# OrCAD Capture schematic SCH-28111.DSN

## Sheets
1 ARDUINO_HEADERS: size C; title: TWR-SHIELD; rev: B; company: Freescale Semiconductor; note: SCH-28111 PDF: SPF-28111; note: 6501 William Cannon Drive West; note: Austin, TX 78735-8598
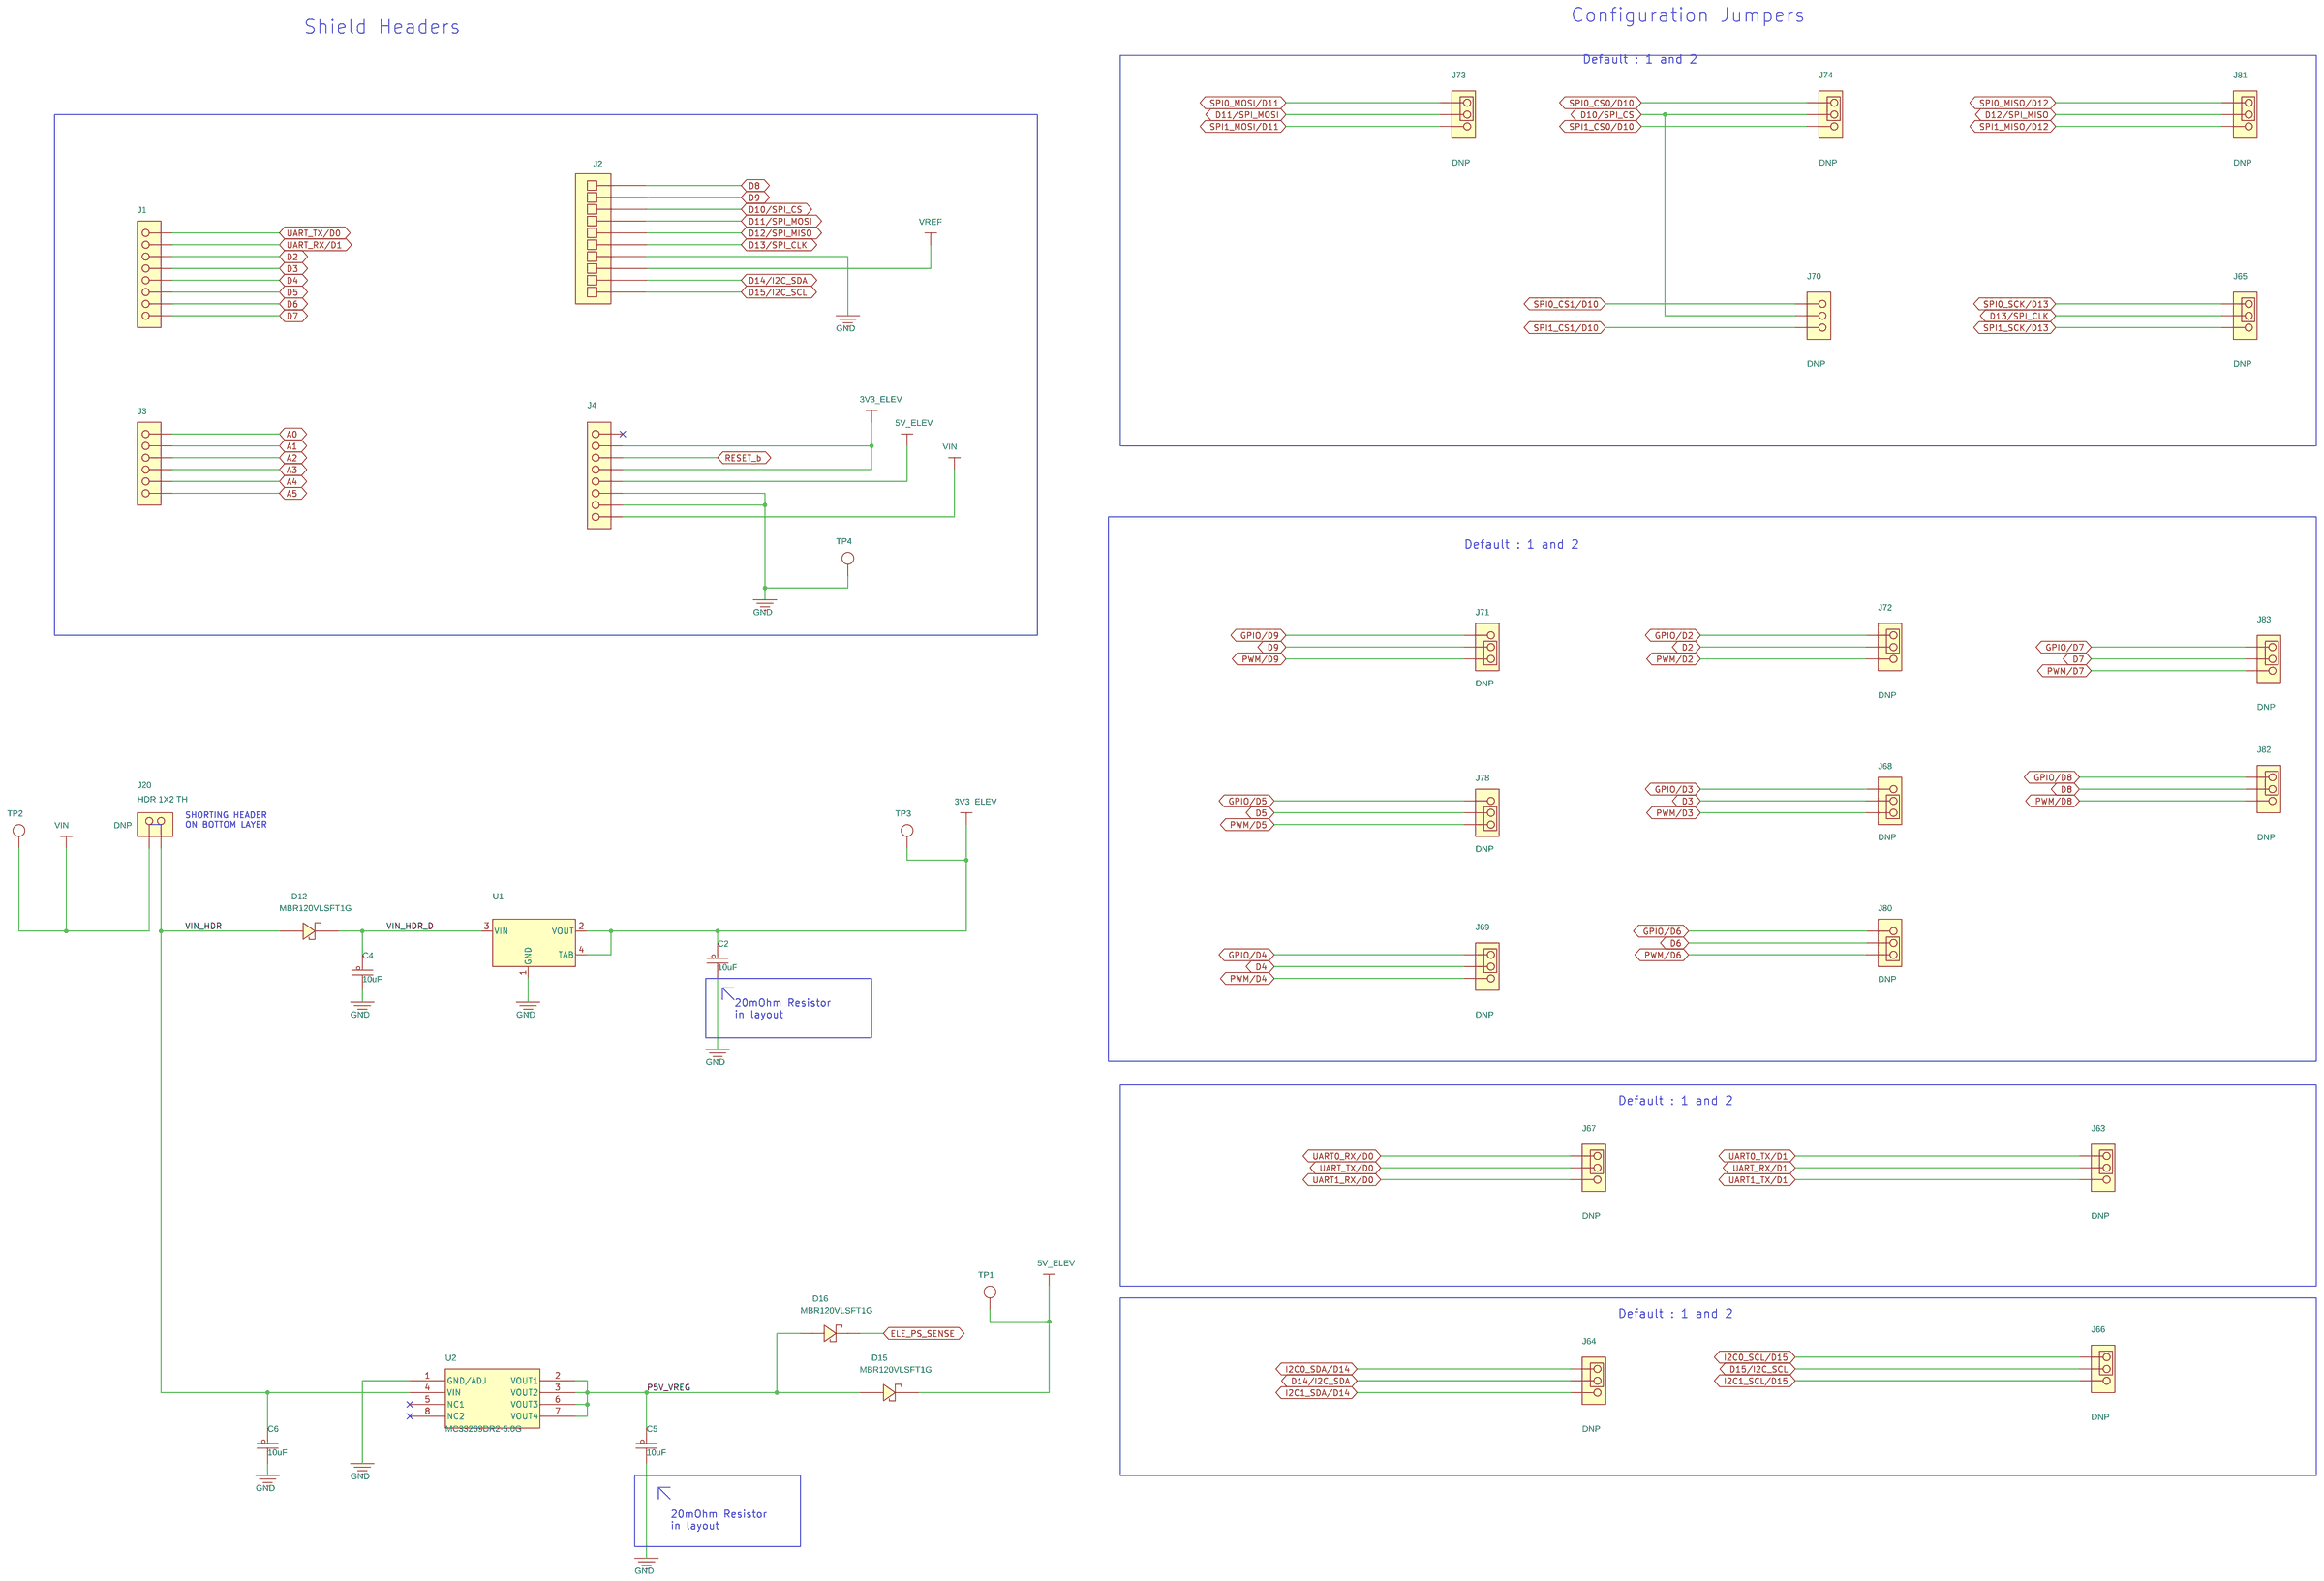
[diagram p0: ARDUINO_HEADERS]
2 ELEVATOR_CONNECTORS: size C
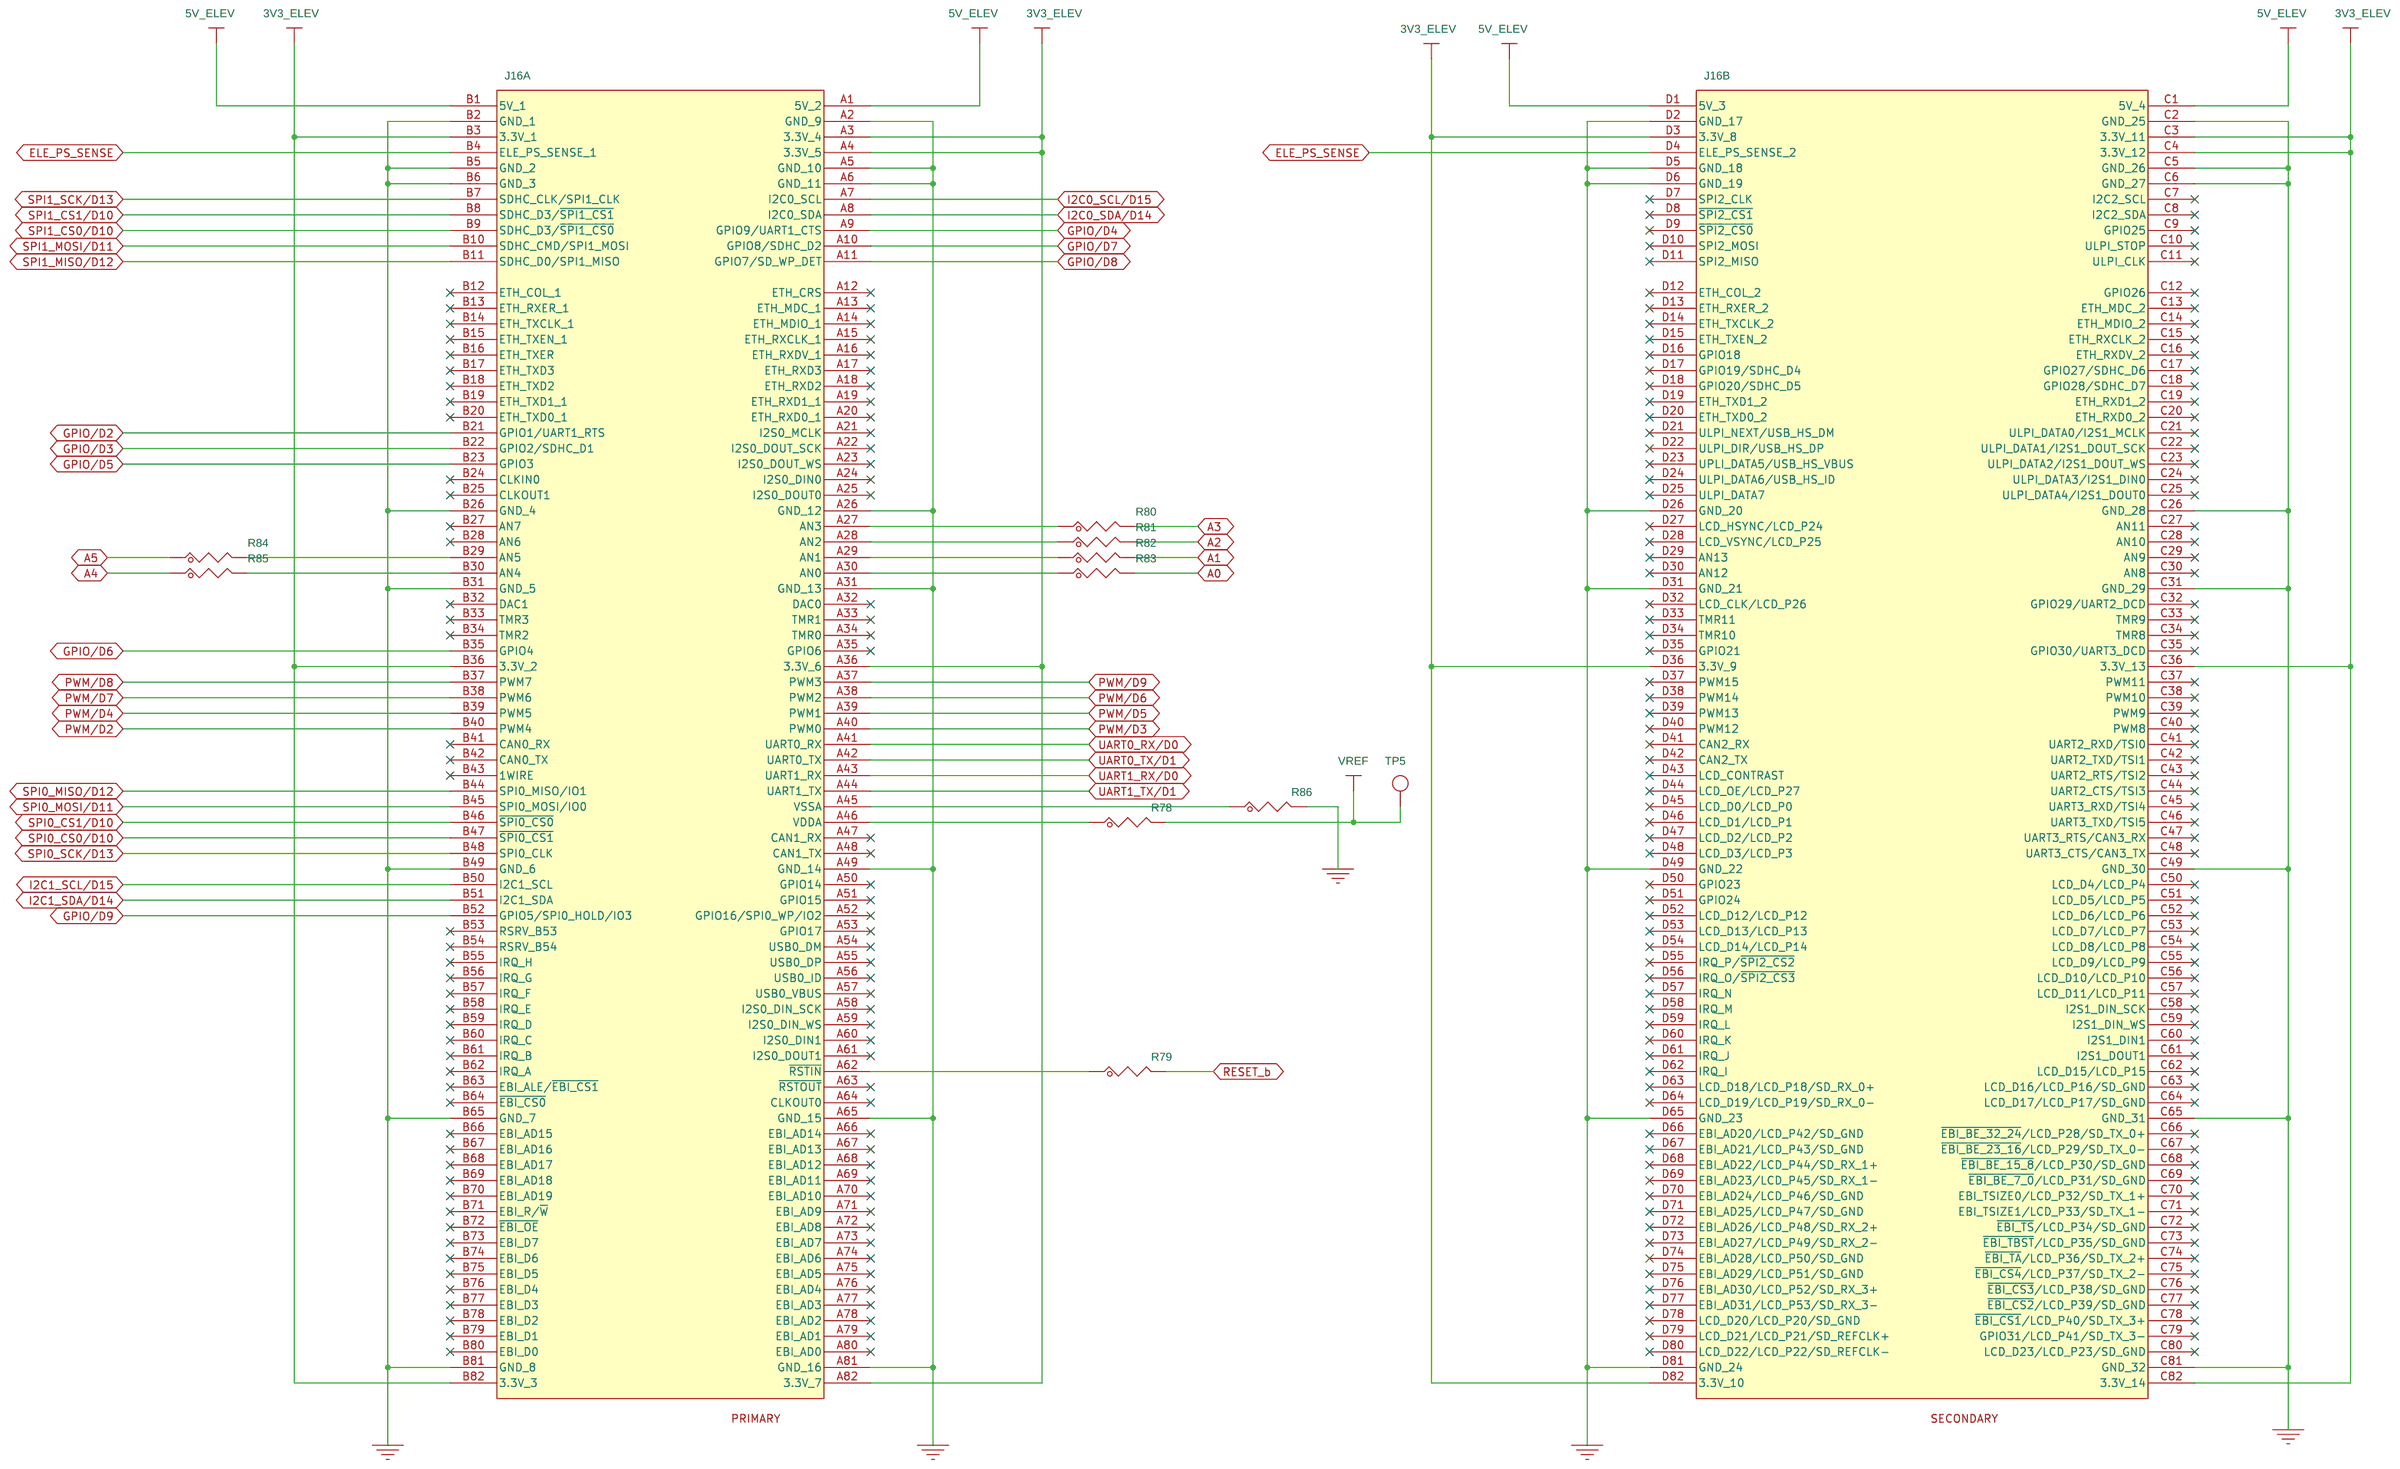
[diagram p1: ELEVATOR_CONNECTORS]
3 01_TABLE_OF_CONTENTS/ REVISION
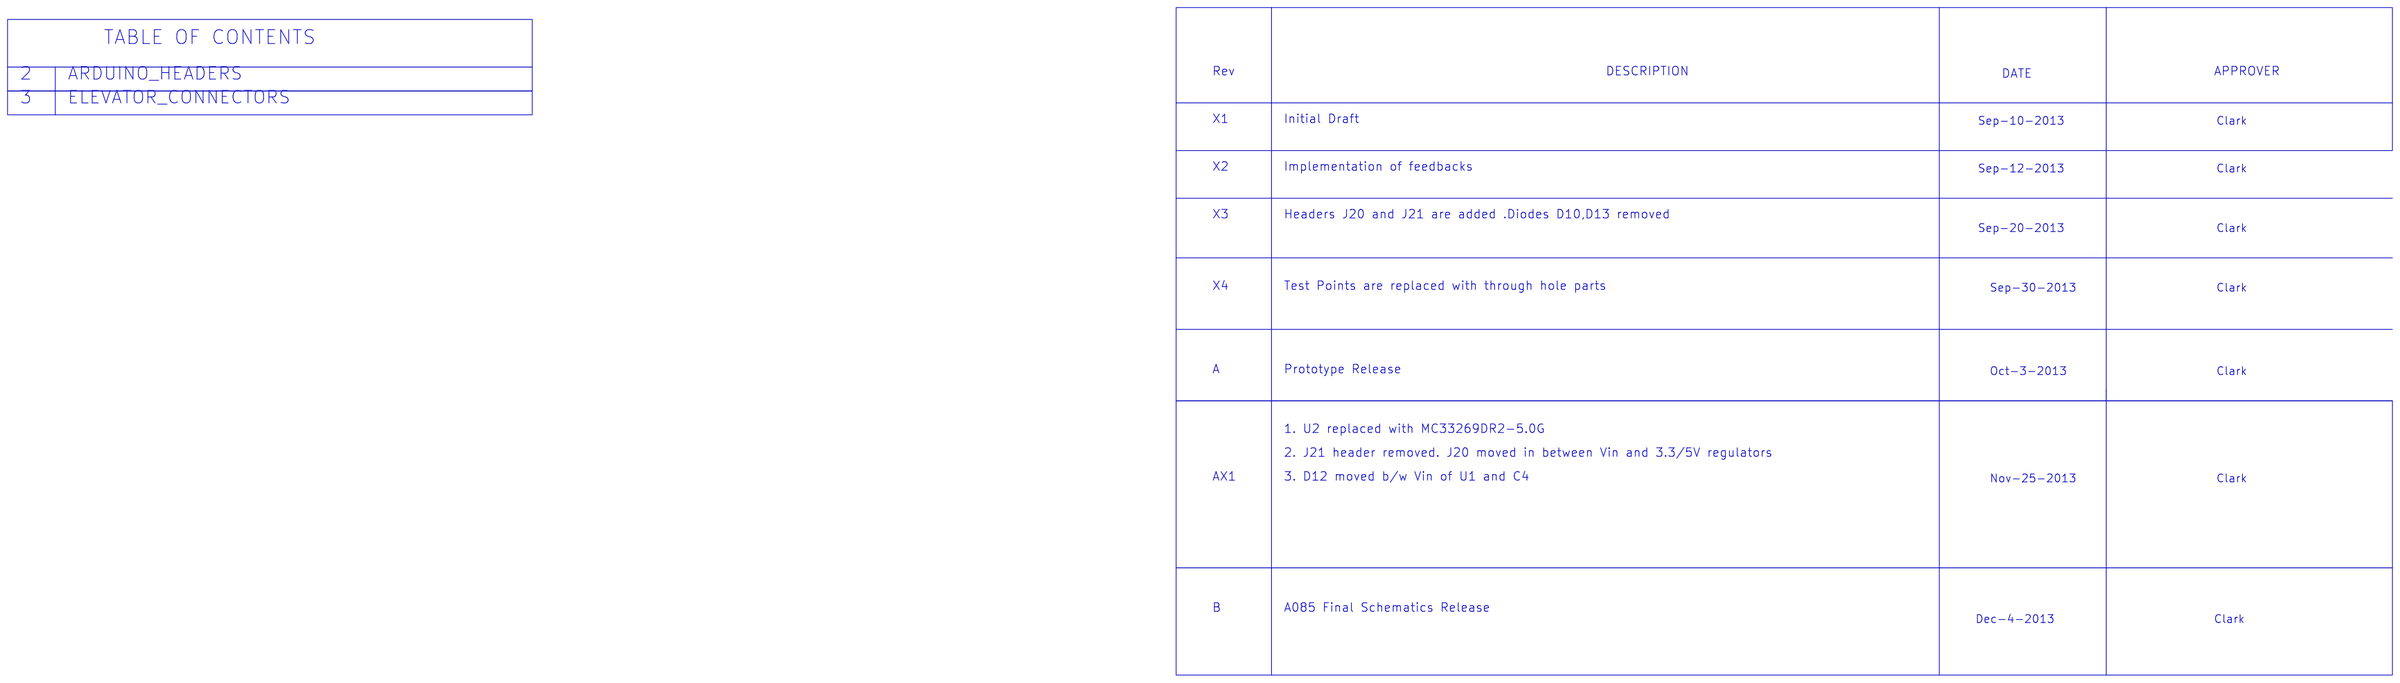
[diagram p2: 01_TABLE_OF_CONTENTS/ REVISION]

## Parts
sheet ARDUINO_HEADERS
C2  10uF  [CC0603_OV]
C4  10uF  [CC0603_OV]
C5  10uF  [CC0603_OV]
C6  10uF  [CC0603_OV]
D12  MBR120VLSFT1G  [SOD-123]
D15  MBR120VLSFT1G  [SOD-123]
D16  MBR120VLSFT1G  [SOD-123]
J1  CON_1X8  [con_1x8_skt_2p54_th]
J2  CON_1X10  [HDR110]
J3  CON_1X6  [con_skt1x6_th]
J4  CON_1X8  [con_1x8_skt_2p54_th]
J20  HDR 1X2 TH  [SH_HDR102_BOTTOM]
J63  HDR 1x3 TH  [hdr103_short1_2]
J64  HDR 1x3 TH  [hdr103_short1_2]
J65  HDR 1x3 TH  [hdr103_short1_2]
J66  HDR 1x3 TH  [hdr103_short1_2]
J67  HDR 1x3 TH  [hdr103_short1_2]
J68  HDR 1x3 TH  [hdr103_short1_2]
J69  HDR 1x3 TH  [hdr103_short1_2]
J70  HDR_1X3  [HDR103]
J71  HDR 1x3 TH  [hdr103_short1_2]
J72  HDR 1x3 TH  [hdr103_short1_2]
J73  HDR 1x3 TH  [hdr103_short1_2]
J74  HDR 1x3 TH  [hdr103_short1_2]
J78  HDR 1x3 TH  [hdr103_short1_2]
J80  HDR 1x3 TH  [hdr103_short1_2]
J81  HDR 1x3 TH  [hdr103_short1_2]
J82  HDR 1x3 TH  [hdr103_short1_2]
J83  HDR 1x3 TH  [hdr103_short1_2]
TP1  TEST POINT WHITE  [TEST_LOOP]
TP2  TEST POINT WHITE  [TEST_LOOP]
TP3  TEST POINT WHITE  [TEST_LOOP]
TP4  TEST POINT WHITE  [TEST_LOOP]
U1  NCP1117ST33T3G  [sot223]
U2  MC33269DR2-5.0G  [so8_1p27_4x5]
sheet ELEVATOR_CONNECTORS
J16  PCI EXPRESS TOWER SYSTEM  [cn2x82_finger_ass]  (sections A,B)
R78  0  [RC0402_25]
R79  0  [RC0402_25]
R80  0  [RC0402_25]
R81  0  [RC0402_25]
R82  0  [RC0402_25]
R83  0  [RC0402_25]
R84  0  [RC0402_25]
R85  0  [RC0402_25]
R86  0  [RC0402_25]
TP5  TEST POINT WHITE  [TEST_LOOP]

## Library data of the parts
C2 C4-C6 = CAP_NP: CAP CER 10UF 10V 20% X5R 0603; AGILE_PN: 150-78609; CAD_APPROVED: Yes; FPLIST: CC0603_OV,CC0603,0603_CC; HEIGHT: 1.016MM; MFG_NAME01: TAIYO YUDEN; MFG_PN01: LMK107BJ106MALTD; ROHS: Yes; VOLTAGE: 10V
D12 D15 D16 = DIODE_SCHTKY: DIODE SCH RECT 1A 20V SMT; AGILE_PN: 480-75997; CAD_APPROVED: Yes; HEIGHT: 1MM; MFG_NAME01: ON SEMICONDUCTOR; ROHS: Yes
J1 J4 = CONN_HDR_8X1: CON 1X8 SKT TH 100MIL SP 335H AU 104L; AGILE_PN: 210-79539; CAD_APPROVED: Yes; HEIGHT: 8.51MM; MFG_NAME01: SAMTEC; MFG_PN01: SSW-108-01-G-S; ROHS: Yes
J2 = RCPT_1X10: CON 1X10 SKT TH 100MIL SP 335H AU; AGILE_PN: 210-75438; CAD_APPROVED: Yes; HEIGHT: 8.51 MM; MFG_NAME01: SAMTEC; MFG_PN01: SSW-110-01-G-S; ROHS: Yes
J3 = CONN_HDR_6X1: CON 1X6 SKT TH 100MIL SP 335H AU 104L; AGILE_PN: 210-79530; CAD_APPROVED: Yes; HEIGHT: 8.76MM; MFG_NAME01: SAMTEC; MFG_PN01: SSW-106-01-G-S; ROHS: Yes
J20 = CONN_HDR_2X1: HDR 1X2 TH 100MIL SP 339H AU 98L; AGILE_PN: 210-75439; ASSY_OPT: DNP; CAD_APPROVED: YES; FPLIST: HDR102,SH_HDR102_BOTTOM; HEIGHT: 8.71 MM; MFG_NAME01: SAMTEC; MFG_PN01: TSW-102-07-G-S; ROHS: Yes
J63-J69 J71-J74 J78 J80-J83 = CONN_HDR_3X1_SHORT: HDR 1X3 TH 100MIL -- NO PART TO ORDER; AGILE_PN: 210-80431; ASSY_OPT: DNP; CAD_APPROVED: Yes; HEIGHT: 8.51 MM; MFG_NAME01: NA; MFG_PN01: NA; ROHS: Yes
J70 = CONN_HDR_3X1: HDR 1X3 TH 100MIL SP 330H AU 98L; AGILE_PN: 210-75442; ASSY_OPT: DNP; CAD_APPROVED: Yes; HEIGHT: 8.38 MM; MFG_NAME01: SAMTEC; MFG_PN01: HTSW-103-07-S-S; ROHS: Yes
TP1-TP5 = TestLoop: TEST POINT WHITE 40 MIL DRILL 180 MIL TH 109L; AGILE_PN: 210-75685; CAD_APPROVED: Yes; HEIGHT: 4.8 MM; MFG_NAME01: COMPONENTS CORPORATION; MFG_PN01: TP-105-01-09; ROHS: Yes
U1 = LD1117AS18: IC VREG LDO 1A 3.3V SOT223; AGILE_PN: 312-80039; CAD_APPROVED: Yes; HEIGHT: 1.8MM; MFG_NAME01: ON Semiconductor; ROHS: Yes
U2 = MC33269D: IC VREG LDO 5V 0.8A 0-20V SO8; AGILE_PN: 315-80046; CAD_APPROVED: Yes; HEIGHT: 1.75MM; MFG_NAME01: ON Semiconductor; ROHS: Yes
J16 = CONN_PCI_XPRESS_X16_328P: CON DUAL 2X82 Edge PCI Express SMT 1MM SP 591H FOR TOWER SYSTEM NOT A PART TO ORDER; AGILE_PN: 211-78844; CAD_APPROVED: Yes; Group: a; HEIGHT: 15.01MM; MFG_NAME01: NA; MFG_PN01: EDGE PCI EXPRESS 164; ROHS: Yes
R78-R86 = RES: RES MF ZERO OHM 1/16W 5% 0402; AGILE_PN: 470-75394; CAD_APPROVED: Yes; FPLIST: RC0402_25,RC0402_HD,RC0402_X2,0402_CC; MFG_NAME01: ROHM; MFG_PN01: MCR01MZPJ000; ROHS: Yes; Tolerance: 5%

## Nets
3V3_ELEV: C2.1 J4.2 J4.4 J16.A3(3.3V_4) J16.A4(3.3V_5) J16.A36(3.3V_6) J16.A82(3.3V_7) J16.B3(3.3V_1) J16.B36(3.3V_2) J16.B82(3.3V_3) J16.C3(3.3V_11) J16.C4(3.3V_12) J16.C36(3.3V_13) J16.C82(3.3V_14) J16.D3(3.3V_8) J16.D36(3.3V_9) J16.D82(3.3V_10) TP3.1(Pin1) U1.2(VOUT) U1.4(TAB)
5V_ELEV: D15.C J4.5 J16.A1(5V_2) J16.B1(5V_1) J16.C1(5V_4) J16.D1(5V_3) TP1.1(Pin1)
GND: C2.2 C4.2 C5.2 C6.2 J2.7 J4.6 J4.7 J16.A2(GND_9) J16.A5(GND_10) J16.A6(GND_11) J16.A26(GND_12) J16.A31(GND_13) J16.A49(GND_14) J16.A65(GND_15) J16.A81(GND_16) J16.B2(GND_1) J16.B5(GND_2) J16.B6(GND_3) J16.B26(GND_4) J16.B31(GND_5) J16.B49(GND_6) J16.B65(GND_7) J16.B81(GND_8) J16.C2(GND_25) J16.C5(GND_26) J16.C6(GND_27) J16.C26(GND_28) J16.C31(GND_29) J16.C49(GND_30) J16.C65(GND_31) J16.C81(GND_32) J16.D2(GND_17) J16.D5(GND_18) J16.D6(GND_19) J16.D26(GND_20) J16.D31(GND_21) J16.D49(GND_22) J16.D65(GND_23) J16.D81(GND_24) R86.2 TP4.1(Pin1) U1.1(GND) U2.1(GND/ADJ)
P5V_VREG: C5.1 D15.A D16.A U2.2(VOUT1) U2.3(VOUT2) U2.6(VOUT3) U2.7(VOUT4)
VIN: J4.8 J20.1 TP2.1(Pin1)
VIN_HDR: C6.1 D12.A J20.2 U2.4(VIN)
VIN_HDR_D: C4.1 D12.C U1.3(VIN)
A0: J3.1 R83.2
A1: J3.2 R82.2
A2: J3.3 R81.2
A3: J3.4 R80.2
A4: J3.5 R85.1
A5: J3.6 R84.1
D2: J1.3 J72.2
D3: J1.4 J68.2
D4: J1.5 J69.2
D5: J1.6 J78.2
D6: J1.7 J80.2
D7: J1.8 J83.2
D8: J2.1 J82.2
D9: J2.2 J71.2
D10/SPI_CS: J2.3 J70.2 J74.2
D11/SPI_MOSI: J2.4 J73.2
D12/SPI_MISO: J2.5 J81.2
D13/SPI_CLK: J2.6 J65.2
D14/I2C_SDA: J2.9 J64.2
D15/I2C_SCL: J2.10 J66.2
ELE_PS_SENSE: D16.C J16.B4(ELE_PS_SENSE_1) J16.D4(ELE_PS_SENSE_2)
GPIO/D2: J16.B21(GPIO1/UART1_RTS) J72.1
GPIO/D3: J16.B22(GPIO2/SDHC_D1) J68.3
GPIO/D4: J16.A9(GPIO9/UART1_CTS) J69.1
GPIO/D5: J16.B23(GPIO3) J78.3
GPIO/D6: J16.B35(GPIO4) J80.3
GPIO/D7: J16.A10(GPIO8/SDHC_D2) J83.1
GPIO/D8: J16.A11(GPIO7/SD_WP_DET) J82.1
GPIO/D9: J16.B52(GPIO5/SPI0_HOLD/IO3) J71.3
I2C0_SCL/D15: J16.A7(I2C0_SCL) J66.1
I2C0_SDA/D14: J16.A8(I2C0_SDA) J64.1
I2C1_SCL/D15: J16.B50(I2C1_SCL) J66.3
I2C1_SDA/D14: J16.B51(I2C1_SDA) J64.3
PWM/D2: J16.B40(PWM4) J72.3
PWM/D3: J16.A40(PWM0) J68.1
PWM/D4: J16.B39(PWM5) J69.3
PWM/D5: J16.A39(PWM1) J78.1
PWM/D6: J16.A38(PWM2) J80.1
PWM/D7: J16.B38(PWM6) J83.3
PWM/D8: J16.B37(PWM7) J82.3
PWM/D9: J16.A37(PWM3) J71.1
RESET_b: J4.3 R79.2
SPI0_CS0/D10: J16.B47(~{SPI0_CS1}) J74.1
SPI0_CS1/D10: J16.B46(~{SPI0_CS0}) J70.1
SPI0_MISO/D12: J16.B44(SPI0_MISO/IO1) J81.1
SPI0_MOSI/D11: J16.B45(SPI0_MOSI/IO0) J73.1
SPI0_SCK/D13: J16.B48(SPI0_CLK) J65.1
SPI1_CS0/D10: J16.B9(SDHC_D3/~{SPI1_CS0}) J74.3
SPI1_CS1/D10: J16.B8(SDHC_D3/~{SPI1_CS1}) J70.3
SPI1_MISO/D12: J16.B11(SDHC_D0/SPI1_MISO) J81.3
SPI1_MOSI/D11: J16.B10(SDHC_CMD/SPI1_MOSI) J73.3
SPI1_SCK/D13: J16.B7(SDHC_CLK/SPI1_CLK) J65.3
UART0_RX/D0: J16.A41(UART0_RX) J67.1
UART0_TX/D1: J16.A42(UART0_TX) J63.1
UART1_RX/D0: J16.A43(UART1_RX) J67.3
UART1_TX/D1: J16.A44(UART1_TX) J63.3
UART_RX/D1: J1.2 J63.2
UART_TX/D0: J1.1 J67.2
VREF: J2.8 R78.2 TP5.1(Pin1)
N13251626: J16.B29(AN5) R84.2
N13251632: J16.B30(AN4) R85.2
N13255265: J16.A27(AN3) R80.1
N13255295: J16.A28(AN2) R81.1
N13255352: J16.A29(AN1) R82.1
N13255371: J16.A30(AN0) R83.1
N13256362: J16.A46(VDDA) R78.1
N13260720: J16.A62(~{RSTIN}) R79.1
N13275722: J16.A45(VSSA) R86.1

Not connected (* = marked no-connect by the designer): J4 1*; J16 A12(ETH_CRS)* A13(ETH_MDC_1)* A14(ETH_MDIO_1)* A15(ETH_RXCLK_1)* A16(ETH_RXDV_1)* A17(ETH_RXD3)* A18(ETH_RXD2)* A19(ETH_RXD1_1)* A20(ETH_RXD0_1)* A21(I2S0_MCLK)* A22(I2S0_DOUT_SCK)* A23(I2S0_DOUT_WS)* A24(I2S0_DIN0)* A25(I2S0_DOUT0)* A32(DAC0)* A33(TMR1)* A34(TMR0)* A35(GPIO6)* A47(CAN1_RX)* A48(CAN1_TX)* A50(GPIO14)* A51(GPIO15)* A52(GPIO16/SPI0_WP/IO2)* A53(GPIO17)* A54(USB0_DM)* A55(USB0_DP)* A56(USB0_ID)* A57(USB0_VBUS)* A58(I2S0_DIN_SCK)* A59(I2S0_DIN_WS)* A60(I2S0_DIN1)* A61(I2S0_DOUT1)* A63(~{RSTOUT})* A64(CLKOUT0)* A66(EBI_AD14)* A67(EBI_AD13)* A68(EBI_AD12)* A69(EBI_AD11)* A70(EBI_AD10)* A71(EBI_AD9)* A72(EBI_AD8)* A73(EBI_AD7)* A74(EBI_AD6)* A75(EBI_AD5)* A76(EBI_AD4)* A77(EBI_AD3)* A78(EBI_AD2)* A79(EBI_AD1)* A80(EBI_AD0)* B12(ETH_COL_1)* B13(ETH_RXER_1)* B14(ETH_TXCLK_1)* B15(ETH_TXEN_1)* B16(ETH_TXER)* B17(ETH_TXD3)* B18(ETH_TXD2)* B19(ETH_TXD1_1)* B20(ETH_TXD0_1)* B24(CLKIN0)* B25(CLKOUT1)* B27(AN7)* B28(AN6)* B32(DAC1)* B33(TMR3)* B34(TMR2)* B41(CAN0_RX)* B42(CAN0_TX)* B43(1WIRE)* B53(RSRV)* B54(RSRV)* B55(IRQ_H)* B56(IRQ_G)* B57(IRQ_F)* B58(IRQ_E)* B59(IRQ_D)* B60(IRQ_C)* B61(IRQ_B)* B62(IRQ_A)* B63(EBI_ALE/~{EBI_CS1})* B64(~{EBI_CS0})* B66(EBI_AD15)* B67(EBI_AD16)* B68(EBI_AD17)* B69(EBI_AD18)* B70(EBI_AD19)* B71(EBI_R/~{W})* B72(~{EBI_OE})* B73(EBI_D7)* B74(EBI_D6)* B75(EBI_D5)* B76(EBI_D4)* B77(EBI_D3)* B78(EBI_D2)* B79(EBI_D1)* B80(EBI_D0)* C7(I2C2_SCL)* C8(I2C2_SDA)* C9(GPIO25)* C10(ULPI_STOP)* C11(ULPI_CLK)* C12(GPIO26)* C13(ETH_MDC_2)* C14(ETH_MDIO_2)* C15(ETH_RXCLK_2)* C16(ETH_RXDV_2)* C17(GPIO27/SDHC_D6)* C18(GPIO28/SDHC_D7)* C19(ETH_RXD1_2)* C20(ETH_RXD0_2)* C21(ULPI_DATA0/I2S1_MCLK)* C22(ULPI_DATA1/I2S1_DOUT_SCK)* C23(ULPI_DATA2/I2S1_DOUT_WS)* C24(ULPI_DATA3/I2S1_DIN0)* C25(ULPI_DATA4/I2S1_DOUT0)* C27(AN11)* C28(AN10)* C29(AN9)* C30(AN8)* C32(GPIO29/UART2_DCD)* C33(TMR9)* C34(TMR8)* C35(GPIO30/UART3_DCD)* C37(PWM11)* C38(PWM10)* C39(PWM9)* C40(PWM8)* C41(UART2_RXD/TSI0)* C42(UART2_TXD/TSI1)* C43(UART2_RTS/TSI2)* C44(UART2_CTS/TSI3)* C45(UART3_RXD/TSI4)* C46(UART3_TXD/TSI5)* C47(UART3_RTS/CAN3_RX)* C48(UART3_CTS/CAN3_TX)* C50(LCD_D4/LCD_P4)* C51(LCD_D5/LCD_P5)* C52(LCD_D6/LCD_P6)* C53(LCD_D7/LCD_P7)* C54(LCD_D8/LCD_P8)* C55(LCD_D9/LCD_P9)* C56(LCD_D10/LCD_P10)* C57(LCD_D11/LCD_P11)* C58(I2S1_DIN_SCK)* C59(I2S1_DIN_WS)* C60(I2S1_DIN1)* C61(I2S1_DOUT1)* C62(LCD_D15/LCD_P15)* C63(LCD_D16/LCD_P16/SD_GND)* C64(LCD_D17/LCD_P17/SD_GND)* C66(~{EBI_BE_32_24}/LCD_P28/SD_TX_0+)* C67(~{EBI_BE_23_16}/LCD_P29/SD_TX_0-)* C68(~{EBI_BE_15_8}/LCD_P30/SD_GND)* C69(~{EBI_BE_7_0}/LCD_P31/SD_GND)* C70(EBI_TSIZE0/LCD_P32/SD_TX_1+)* C71(EBI_TSIZE1/LCD_P33/SD_TX_1-)* C72(~{EBI_TS}/LCD_P34/SD_GND)* C73(~{EBI_TBST}/LCD_P35/SD_GND)* C74(~{EBI_TA}/LCD_P36/SD_TX_2+)* C75(~{EBI_CS4}/LCD_P37/SD_TX_2-)* C76(~{EBI_CS3}/LCD_P38/SD_GND)* C77(~{EBI_CS2}/LCD_P39/SD_GND)* C78(~{EBI_CS1}/LCD_P40/SD_TX_3+)* C79(GPIO31/LCD_P41/SD_TX_3-)* C80(LCD_D23/LCD_P23/SD_GND)* D7(SPI2_CLK)* D8(~{SPI2_CS1})* D9(~{SPI2_CS0})* D10(SPI2_MOSI)* D11(SPI2_MISO)* D12(ETH_COL_2)* D13(ETH_RXER_2)* D14(ETH_TXCLK_2)* D15(ETH_TXEN_2)* D16(GPIO18)* D17(GPIO19/SDHC_D4)* D18(GPIO20/SDHC_D5)* D19(ETH_TXD1_2)* D20(ETH_TXD0_2)* D21(ULPI_NEXT/USB_HS_DM)* D22(ULPI_DIR/USB_HS_DP)* D23(UPLI_DATA5/USB_HS_VBUS)* D24(ULPI_DATA6/USB_HS_ID)* D25(ULPI_DATA7)* D27(LCD_HSYNC/LCD_P24)* D28(LCD_VSYNC/LCD_P25)* D29(AN13)* D30(AN12)* D32(LCD_CLK/LCD_P26)* D33(TMR11)* D34(TMR10)* D35(GPIO21)* D37(PWM15)* D38(PWM14)* D39(PWM13)* D40(PWM12)* D41(CAN2_RX)* D42(CAN2_TX)* D43(LCD_CONTRAST)* D44(LCD_OE/LCD_P27)* D45(LCD_D0/LCD_P0)* D46(LCD_D1/LCD_P1)* D47(LCD_D2/LCD_P2)* D48(LCD_D3/LCD_P3)* D50(GPIO23)* D51(GPIO24)* D52(LCD_D12/LCD_P12)* D53(LCD_D13/LCD_P13)* D54(LCD_D14/LCD_P14)* D55(IRQ_P/~{SPI2_CS2})* D56(IRQ_O/~{SPI2_CS3})* D57(IRQ_N)* D58(IRQ_M)* D59(IRQ_L)* D60(IRQ_K)* D61(IRQ_J)* D62(IRQ_I)* D63(LCD_D18/LCD_P18/SD_RX_0+)* D64(LCD_D19/LCD_P19/SD_RX_0-)* D66(EBI_AD20/LCD_P42/SD_GND)* D67(EBI_AD21/LCD_P43/SD_GND)* D68(EBI_AD22/LCD_P44/SD_RX_1+)* D69(EBI_AD23/LCD_P45/SD_RX_1-)* D70(EBI_AD24/LCD_P46/SD_GND)* D71(EBI_AD25/LCD_P47/SD_GND)* D72(EBI_AD26/LCD_P48/SD_RX_2+)* D73(EBI_AD27/LCD_P49/SD_RX_2-)* D74(EBI_AD28/LCD_P50/SD_GND)* D75(EBI_AD29/LCD_P51/SD_GND)* D76(EBI_AD30/LCD_P52/SD_RX_3+)* D77(EBI_AD31/LCD_P53/SD_RX_3-)* D78(LCD_D20/LCD_P20/SD_GND)* D79(LCD_D21/LCD_P21/SD_REFCLK+)* D80(LCD_D22/LCD_P22/SD_REFCLK-)*; U2 5(NC1)* 8(NC2)*

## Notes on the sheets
sheet 1
- Configuration Jumpers
- Shield Headers
- Default : 1 and 2
- Default : 1 and 2
- SHORTING HEADER
  ON BOTTOM LAYER
- 20mOhm Resistor
  in layout
- Default : 1 and 2
- Default : 1 and 2
- 20mOhm Resistor
  in layout
sheet 3
- TABLE OF CONTENTS
- 2
- ARDUINO_HEADERS
- Rev
- DESCRIPTION
- DATE
- APPROVER
- 3
- ELEVATOR_CONNECTORS
- X1
- Initial Draft
- Sep-10-2013
- Clark
- X2
- Implementation of feedbacks
- Sep-12-2013
- Clark
- X3
- Headers J20 and J21 are added .Diodes D10,D13 removed
- Sep-20-2013
- Clark
- X4
- Test Points are replaced with through hole parts
- Sep-30-2013
- Clark
- A
- Prototype Release
- Oct-3-2013
- Clark
- 1. U2 replaced with MC33269DR2-5.0G
- 2. J21 header removed. J20 moved in between Vin and 3.3/5V regulators
- AX1
- 3. D12 moved b/w Vin of U1 and C4
- Nov-25-2013
- Clark
- B
- A085 Final Schematics Release
- Dec-4-2013
- Clark
